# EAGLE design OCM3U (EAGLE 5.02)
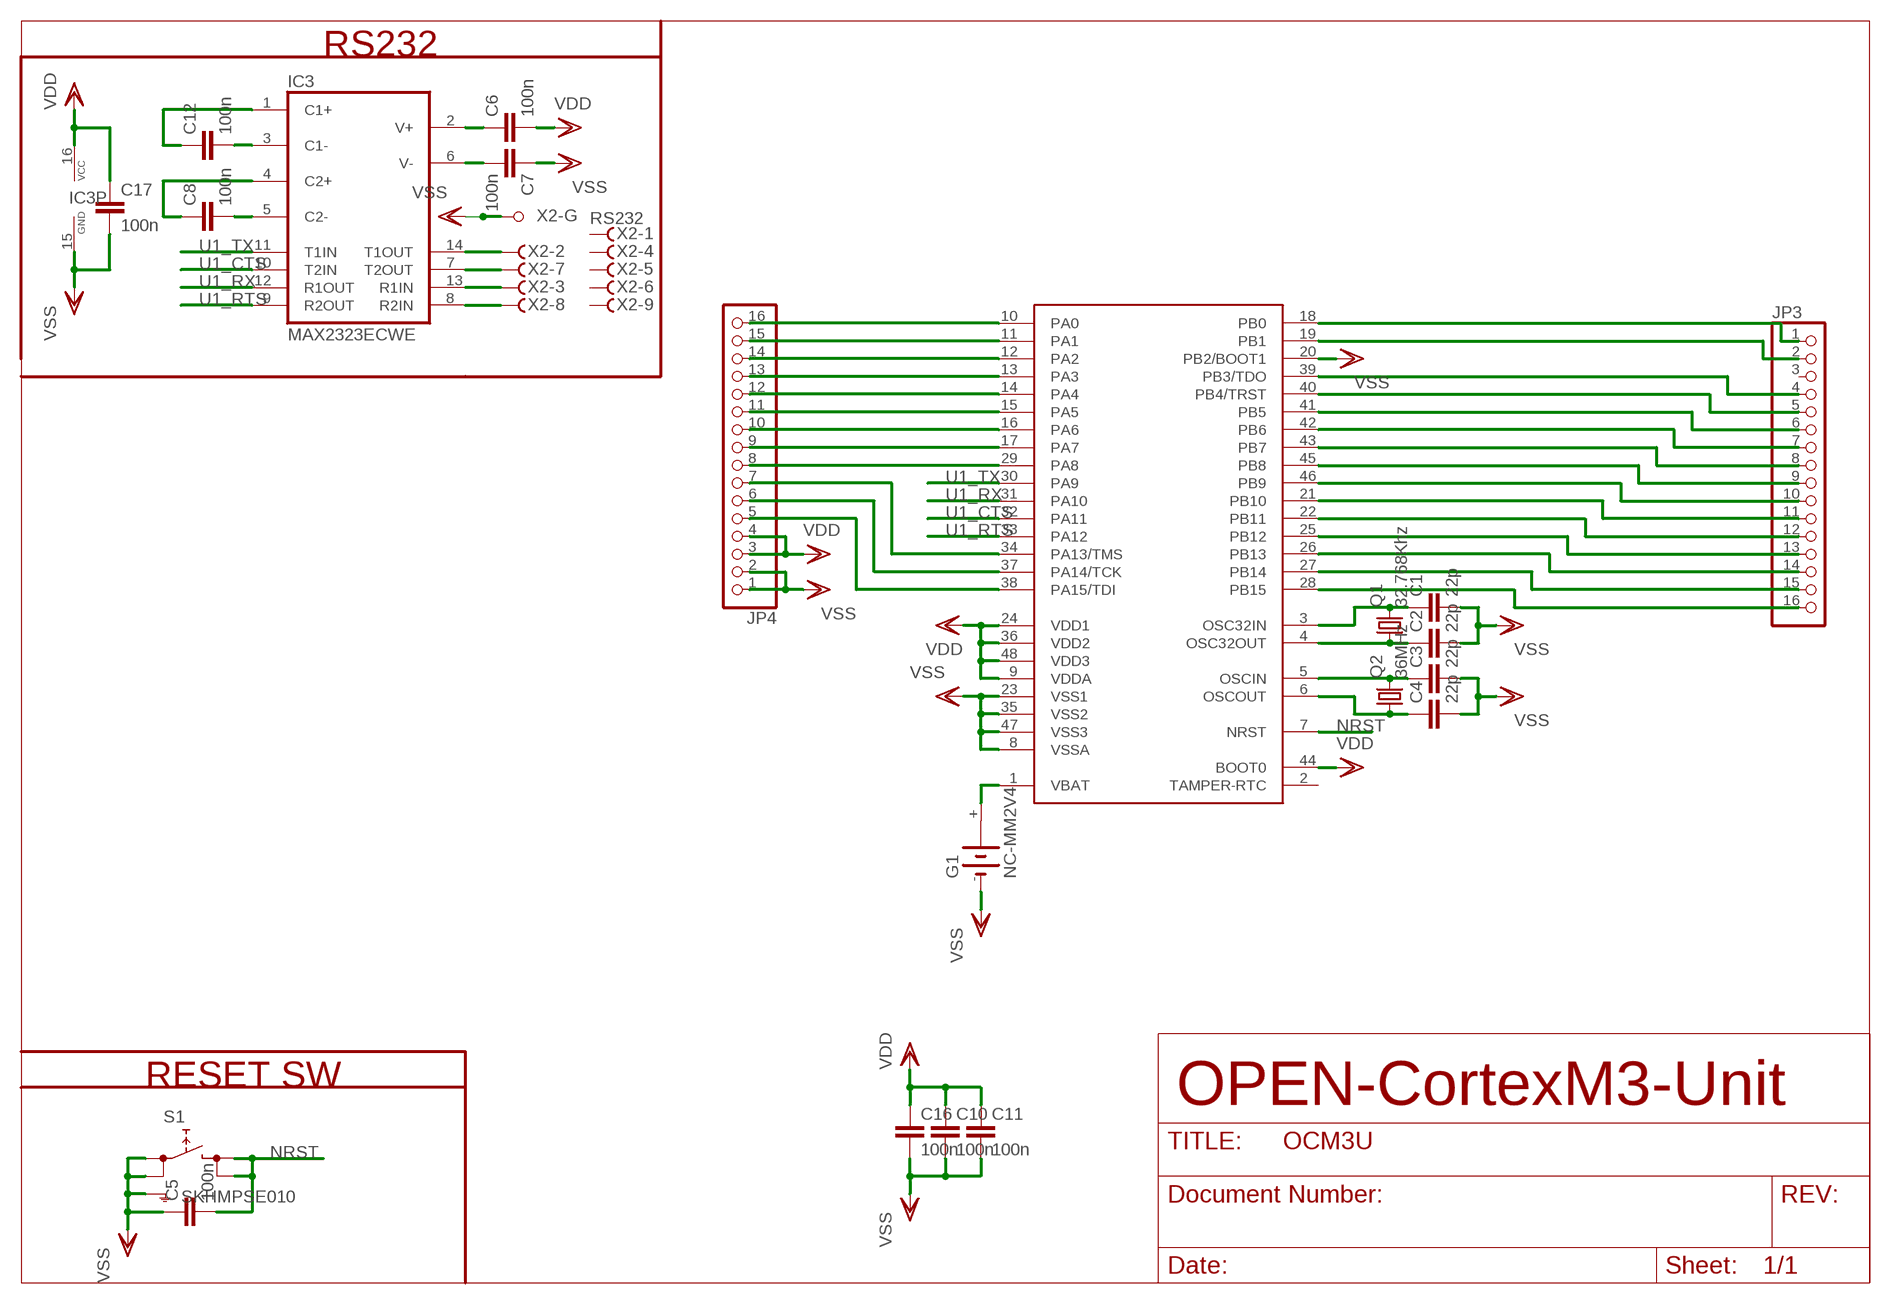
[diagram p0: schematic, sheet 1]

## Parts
C1  22p  C-EUC0805  [C0805]
C2  22p  C-EUC0805  [C0805]
C3  22p  C-EUC0805  [C0805]
C4  22p  C-EUC0805  [C0805]
C5  100n  C-EUC0805  [C0805]
C6  100n  C-EUC0805  [C0805]
C7  100n  C-EUC0805  [C0805]
C8  100n  C-EUC0805  [C0805]
C10  100n  C-EUC0805  [C0805]
C11  100n  C-EUC0805  [C0805]
C12  100n  C-EUC0805  [C0805]
C16  100n  C-EUC0805  [C0805]
C17  100n  C-EUC0805  [C0805]
G1  NC-MM2V4  [NC-MM]
IC3  MAX2323ECWE  MAX232ECWE  [SO16L]
JP3  PINHD-1X16  [1X16]
JP4  PINHD-1X16  [1X16]
Q1  32.768Khz  CRYSTALHC49UP  [HC49UP]
Q2  36MHz  CRYSTALHC49UP  [HC49UP]
S1  SKHMPSE010  [SKHMPXE010]
U$1  STM32F101C8T6  [LQFP48]
X2  RS232  F09HPS  [F09HP]

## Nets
N$1: G1.+ U$1.1(VBAT)
N$4: C1.1 Q1.2 U$1.3(OSC32IN)
N$5: C2.1 Q1.1 U$1.4(OSC32OUT)
N$6: C3.1 Q2.2 U$1.5(OSCIN)
N$7: C4.1 Q2.1 U$1.6(OSCOUT)
N$8: IC3.13(R1IN) X2.3(-3:F)
N$9: IC3.14(T1OUT) X2.2(-2:F)
N$10: IC3.7(T2OUT) X2.7(-7:F)
N$11: IC3.8(R2IN) X2.8(-8:F)
N$12: C6.1 IC3.2(V+)
N$13: C7.2 IC3.6(V-)
N$14: C12.2 IC3.3(C1-)
N$15: C12.1 IC3.1(C1+)
N$16: C8.1 IC3.4(C2+)
N$17: C8.2 IC3.5(C2-)
N$18: JP3.16 U$1.28(PB15)
N$19: JP3.15 U$1.27(PB14)
N$20: JP3.9 U$1.45(PB8)
N$21: JP3.14 U$1.26(PB13)
N$22: JP3.13 U$1.25(PB12)
N$23: JP3.12 U$1.22(PB11)
N$24: JP3.11 U$1.21(PB10)
N$25: JP3.10 U$1.46(PB9)
N$27: JP3.8 U$1.43(PB7)
N$28: JP3.7 U$1.42(PB6)
N$29: JP3.6 U$1.41(PB5)
N$30: JP3.2 U$1.19(PB1)
N$31: JP3.1 U$1.18(PB0)
N$32: JP4.16 U$1.10(PA0)
N$33: JP4.15 U$1.11(PA1)
N$34: JP4.14 U$1.12(PA2)
N$35: JP4.13 U$1.13(PA3)
N$36: JP4.12 U$1.14(PA4)
N$37: JP4.11 U$1.15(PA5)
N$38: JP4.10 U$1.16(PA6)
N$39: JP4.9 U$1.17(PA7)
N$40: JP4.8 U$1.29(PA8)
N$44: JP3.5 U$1.40(PB4/TRST)
N$45: JP3.4 U$1.39(PB3/TDO)
N$46: JP4.7 U$1.34(PA13/TMS)
N$47: JP4.6 U$1.37(PA14/TCK)
N$48: JP4.5 U$1.38(PA15/TDI)
NRST: C5.2 S1.3(2.1) S1.4(2.2) U$1.7(NRST)
U1_CTS: IC3.10(T2IN) U$1.32(PA11)
U1_RTS: IC3.9(R2OUT) U$1.33(PA12)
U1_RX: IC3.12(R1OUT) U$1.31(PA10)
U1_TX: IC3.11(T1IN) U$1.30(PA9)
VDD: C6.2 C10.1 C11.1 C16.1 C17.1 IC3.16(VCC) JP4.3 JP4.4 U$1.9(VDDA) U$1.24(VDD1) U$1.36(VDD2) U$1.44(BOOT0) U$1.48(VDD3)
VSS: C1.2 C2.2 C3.2 C4.2 C5.1 C7.1 C10.2 C11.2 C16.2 C17.2 G1.- IC3.15(GND) JP4.1 JP4.2 S1.1(1.1) S1.2(1.2) S1.5(SH) U$1.8(VSSA) U$1.20(PB2/BOOT1) U$1.23(VSS1) U$1.35(VSS2) U$1.47(VSS3) X2.G1(-G:G1) X2.G2(-G:G2)
Unconnected: G1.+@1(+) JP3.3 U$1.2(TAMPER-RTC) X2.1(-1:F) X2.4(-4:F) X2.5(-5:F) X2.6(-6:F) X2.9(-9:F)

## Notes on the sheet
- RS232
- RESET SW
- OPEN-CortexM3-Unit

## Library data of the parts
C1-C8 C10-C12 C16 C17 = rcl:C-EU: CAPACITOR, European symbol
G1 = battery:NC-MM2V4: NC ACCU Sonnenschein Mini-Memo NC-MM 2.4 to 4.8 R5 Sonnenschein
IC3 = maxim:MAX232ECWE: RS232 TRANSEIVER
JP3 JP4 = pinhead:PINHD-1X16: PIN HEADER
Q1 Q2 = crystal:CRYSTAL: CRYSTAL
S1 = switch:SKHMP*E010: 6.2 X 6.5mm TACT Switch (SMD) Source: http://www3.alps.co.jp/WebObjects/catalog.woa/PDF/E/Switch/Tact/SKHM/SKHM.PDF
U$1 = stm32F101xx:STM32F101C8T6
X2 = con-subd:F09HPS: SUB-D

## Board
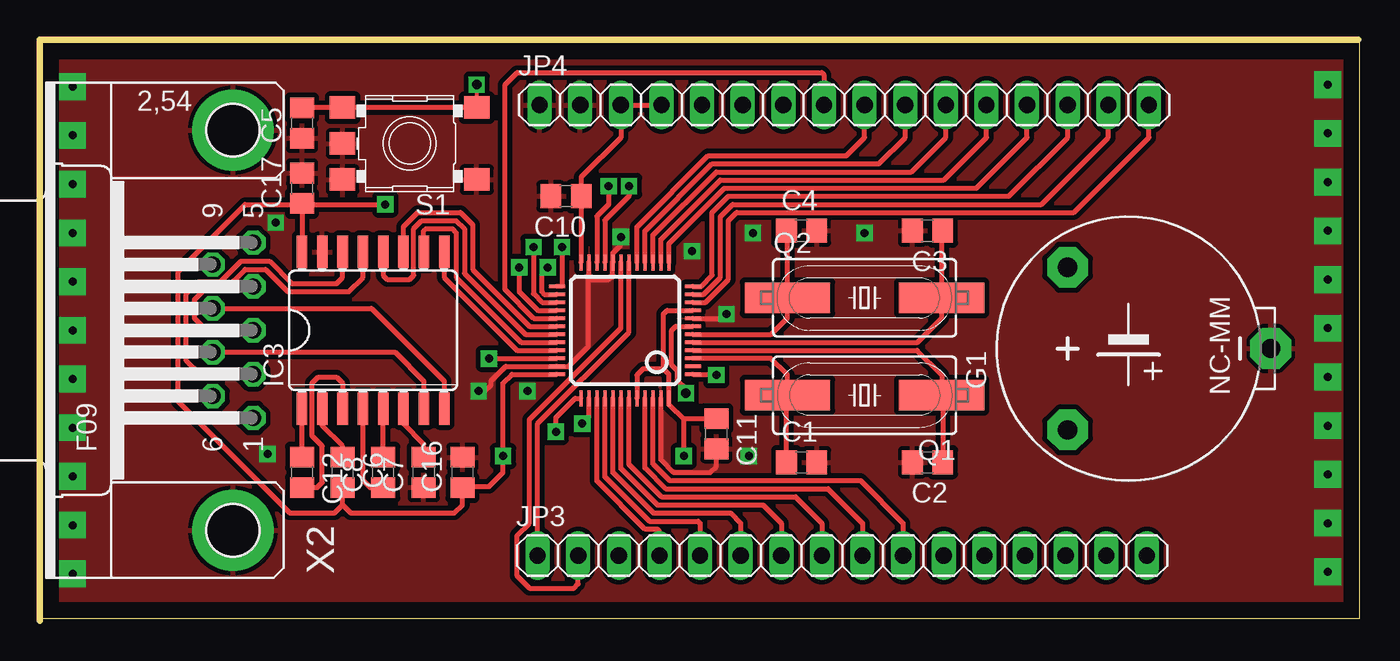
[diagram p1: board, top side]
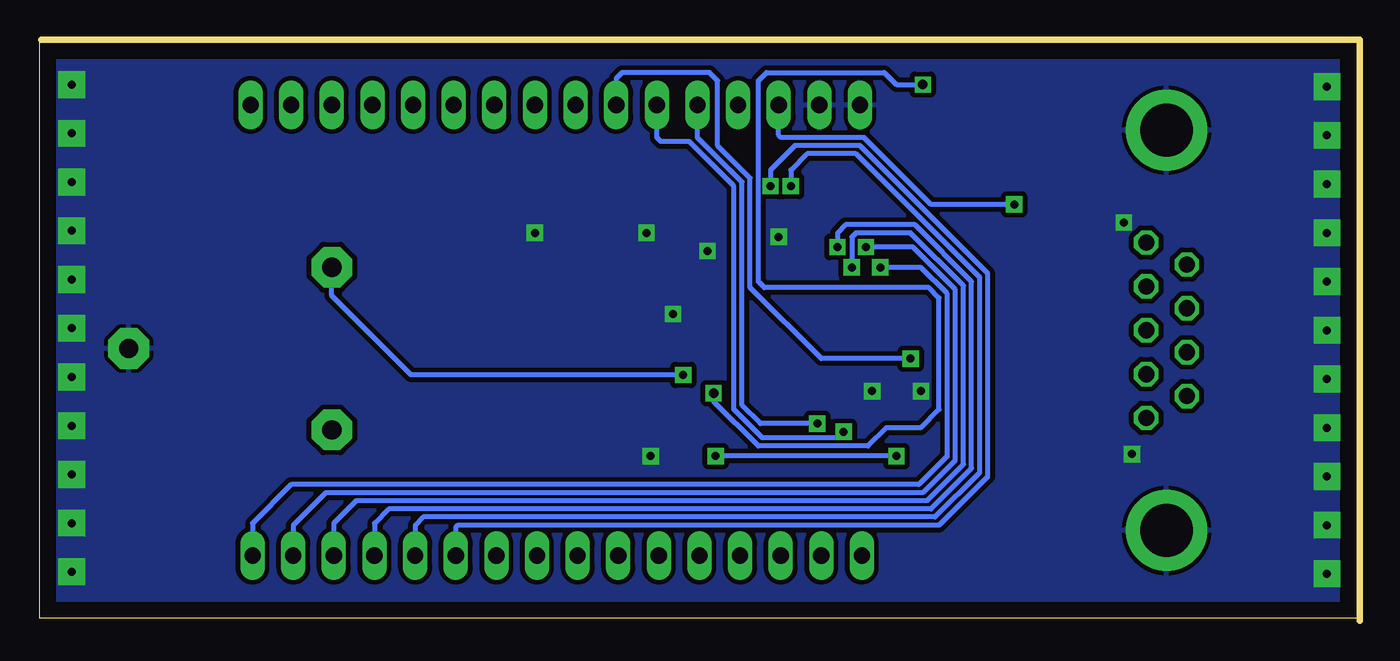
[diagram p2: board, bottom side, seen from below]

Size 82.51 x 36.32 mm. Coordinates in mm from the lower left corner, seen from the top.
Outline: 0,0 0,36.32 82.42,36.32
Outline: 0.04,0.13 82.51,0.13 82.51,36.19 0.04,36.19 0.04,0.13
Copper layers (1*16): Top 0.035mm / dielectric 1.5mm / Bottom 0.035mm
Design rules "default": minimum track width 10mil, minimum drill 24mil, track to track 8mil, track to pad 8mil, pad to pad 8mil, via to via 8mil, smd to smd 8mil, copper to edge 40mil, drill to drill 8mil, minimum pad ring 10mil, minimum via ring 8mil, stop-mask expansion 4mil, vias tented up to drill 0mil, thermal gap 10mil

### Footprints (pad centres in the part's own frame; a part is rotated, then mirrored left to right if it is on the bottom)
C0805 = smd 1.3 x 1.5: 1 -0.95,0; 2 0.95,0
NC-MM = drill 1.194 pad 2.54 octagon: + 5.08,3.81; +@1 -5.08,3.81; - 0,-8.89
SO16L = smd 0.66 x 2.032: 1 -4.445,-4.902; 2 -3.175,-4.902; 3 -1.905,-4.902; 4 -0.635,-4.902; 5 0.635,-4.902; 6 1.905,-4.902; 7 3.175,-4.902; 8 4.445,-4.902; 9 4.445,4.902; 10 3.175,4.902; 11 1.905,4.902; 12 0.635,4.902; 13 -0.635,4.902; 14 -1.905,4.902; 15 -3.175,4.902; 16 -4.445,4.902
1X16 = drill 1.016 long: 1 -19.05,0; 2 -16.51,0; 3 -13.97,0; 4 -11.43,0; 5 -8.89,0; 6 -6.35,0; 7 -3.81,0; 8 -1.27,0; 9 1.27,0; 10 3.81,0; 11 6.35,0; 12 8.89,0; 13 11.43,0; 14 13.97,0; 15 16.51,0; 16 19.05,0
HC49UP = smd 5.334 x 1.93: 1 -4.826,0; 2 4.826,0
SKHMPXE010 = smd 1.6 x 1.4: 1 -4.2,2.25; 2 4.2,2.25; 3 -4.2,-2.25; 4 4.2,-2.25; 5 4.2,0
LQFP48 = smd 0.2 x 1: 1 -2.75,-4.25; 2 -2.25,-4.25; 3 -1.75,-4.25; 4 -1.25,-4.25; 5 -0.75,-4.25; 6 -0.25,-4.25; 7 0.25,-4.25; 8 0.75,-4.25; 9 1.25,-4.25; 10 1.75,-4.25; 11 2.25,-4.25; 12 2.75,-4.25; 25 2.75,4.25; 26 2.25,4.25; 27 1.75,4.25; 28 1.25,4.25; 29 0.75,4.25; 30 0.25,4.25; 31 -0.25,4.25; 32 -0.75,4.25; 33 -1.25,4.25; 34 -1.75,4.25; 35 -2.25,4.25; 36 -2.75,4.25 | smd 1 x 0.2: 13 4.25,-2.75; 14 4.25,-2.25; 15 4.25,-1.75; 16 4.25,-1.25; 17 4.25,-0.75; 18 4.25,-0.25; 19 4.25,0.25; 20 4.25,0.75; 21 4.25,1.25; 22 4.25,1.75; 23 4.25,2.25; 24 4.25,2.75; 37 -4.25,2.75; 38 -4.25,2.25; 39 -4.25,1.75; 40 -4.25,1.25; 41 -4.25,0.75; 42 -4.25,0.25; 43 -4.25,-0.25; 44 -4.25,-0.75; 45 -4.25,-1.25; 46 -4.25,-1.75; 47 -4.25,-2.25; 48 -4.25,-2.75
F09HP = drill 1.016 octagon: 1 -5.486,-1.27; 2 -2.743,-1.27; 3 0,-1.27; 4 2.743,-1.27; 5 5.486,-1.27; 6 -4.115,1.27; 7 -1.372,1.27; 8 1.372,1.27; 9 4.115,1.27 | drill 3.302 pad 5.08 round: G1 -12.522,0; G2 12.522,0

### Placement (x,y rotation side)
C1  47.62,9.91 0 top
C2  55.5,9.91 180 top
C3  55.5,24.38 180 top
C4  47.62,24.38 0 top
C5  16.38,31.11 90 top
C6  18.92,9.27 270 top
C7  24,9.27 90 top
C8  21.46,9.27 90 top
C10  32.89,26.54 180 top
C11  42.29,11.68 270 top
C12  16.38,9.27 270 top
C16  26.42,9.27 90 top
C17  16.38,27.05 90 top
G1  68.07,17.02 90 top
IC3  20.83,18.16 0 top
JP3  50.16,4.06 0 top
JP4  50.29,32.26 0 top
Q1  51.56,14.1 180 top
Q2  51.56,20.19 0 top
S1  23.11,29.84 180 top
U$1  36.58,18.16 90 top
X2  12.06,18.16 90 top

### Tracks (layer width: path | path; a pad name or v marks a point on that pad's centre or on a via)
N$1  (via drill 0.5 pad 1.02)
  Top 0.305: U$1.1 42.25,15.41 v42.29,15.37
  Bottom 0.305: v42.29,15.37 59.31,15.37 64.26,20.32 G1.+
N$4
  Top 0.305: U$1.3 45.69,16.41 46.74,15.37 46.74,14.22 46.86,14.1 Q1.2 46.61,14.1 46.67,14.03 C1.1
N$5
  Top 0.305: U$1.4 54.84,16.91 56.39,15.37 56.39,14.22 | 56.39,13.84 Q1.1 56.39,14.22 | C2.1 56.45,14.16 56.39,14.22
N$6
  Top 0.305: U$1.5 54.88,17.41 56.39,18.92 Q2.2 | Q2.2 56.26,20.32 | C3.1 56.13,24.38 56.39,24.13 Q2.2
N$7
  Top 0.305: U$1.6 45.72,17.91 46.74,18.92 Q2.1 | Q2.1 46.74,20.32 | C4.1 46.74,24.38 Q2.1
N$8
  Top 0.254: IC3.13 20.19,23.24
  Top 0.305: X2.3 10.41,18.16 9.65,18.92 9.65,20.07 10.29,20.7 11.56,20.7 12.83,21.97 14.1,21.97 15.49,20.57 19.3,20.57 20.19,21.46 IC3.13
N$9
  Top 0.305: X2.2 9.98,15.42 9.14,16.26 9.14,20.45 9.91,21.21 11.3,21.21 12.57,22.48 14.35,22.48 15.75,21.08 18.54,21.08 18.92,21.46 IC3.14
N$10
  Top 0.254: IC3.7 24,13.08
  Top 0.305: X2.7 22.2,16.79 24,14.99 IC3.7
N$11
  Top 0.254: IC3.8 25.27,13.08
  Top 0.305: X2.8 20.73,19.53 25.27,14.99 25.27,13.46 25.4,13.33 IC3.8
N$12
  Top 0.305: IC3.2 17.65,12.19 18.92,10.92 C6.1
N$13
  Top 0.305: IC3.6 22.73,12.32 24,11.05 24,10.41 23.88,10.29 C7.2
N$14
  Top 0.305: C12.2 17.34,8.32 17.65,8.64 17.65,10.92 17.02,11.56 17.02,14.86 17.4,15.24 18.54,15.24 18.92,14.86 18.92,13.46 19.05,13.33 IC3.3
N$15
  Top 0.305: C12.1 IC3.1
N$16
  Top 0.305: C8.1 20.64,8.32 20.19,8.76 20.19,12.95 20.07,13.08 20.19,13.21 IC3.4
N$17
  Top 0.305: C8.2 IC3.5
N$18  (via drill 0.5 pad 1.02)
  Top 0.305: U$1.28 31.14,19.41 29.97,20.57 v29.97,22.1
  Bottom 0.305: v29.97,22.1 27.43,22.1 25.78,20.45 25.78,10.29 27.56,8.51 66.8,8.51 69.22,6.1 JP3.16
N$19  (via drill 0.5 pad 1.02)
  Top 0.305: U$1.27 31.4,19.91 30.86,20.45 v30.86,23.37
  Bottom 0.305: v30.86,23.37 27.94,23.37 25.27,20.7 25.27,10.03 27.31,8 64.64,8 66.68,5.97 JP3.15
N$20
  Top 0.305: U$1.45 37.83,9.54 39.12,8.25 49.28,8.25 51.43,6.1 JP3.9 51.43,3.94
N$21  (via drill 0.5 pad 1.02)
  Top 0.305: U$1.26 31.53,20.41 31.37,20.57 31.37,22.1 v31.75,22.1
  Bottom 0.305: v31.75,22.1 31.75,24 31.5,24.26 28.07,24.26 24.77,20.95 24.77,9.78 27.05,7.49 62.74,7.49 64.14,6.1 JP3.14
N$22  (via drill 0.5 pad 1.02)
  Top 0.305: U$1.25 32.64,20.91 v32.64,23.37
  Bottom 0.305: v32.64,23.37 32.64,24.26 32.13,24.77 27.81,24.77 24.26,21.21 24.26,9.53 26.8,6.98 60.71,6.98 61.59,6.1 61.59,4.32 61.72,4.19 JP3.13
N$23  (via drill 0.5 pad 1.02)
  Top 0.305: U$1.22 34.83,25.3 35.56,26.04 v35.56,27.18
  Bottom 0.305: v35.56,27.18 35.56,28.19 34.54,29.21 31.5,29.21 23.75,21.46 23.75,9.27 26.54,6.48 58.55,6.48 59.05,5.97 JP3.12
N$24  (via drill 0.5 pad 1.02)
  Top 0.305: U$1.21 35.33,25.04 36.83,26.54 v36.83,27.18
  Bottom 0.305: v36.83,27.18 36.83,28.19 35.31,29.72 31.24,29.72 23.24,21.72 23.24,9.02 26.29,5.97 56.39,5.97 56.52,5.84 JP3.11
N$25
  Top 0.305: U$1.46 38.33,9.81 39.37,8.76 51.31,8.76 53.98,6.1 JP3.10 53.98,3.94
N$27
  Top 0.305: U$1.43 36.83,9.78 38.86,7.75 47.24,7.75 48.89,6.1 JP3.8
N$28
  Top 0.305: U$1.42 36.33,9.52 38.61,7.24 45.21,7.24 46.35,6.1 JP3.7
N$29
  Top 0.305: U$1.41 35.83,9.26 38.35,6.73 43.18,6.73 43.81,6.1 JP3.6
N$30
  Top 0.305: U$1.19 36.33,18.29 30.61,12.57 30.61,6.1 29.85,5.33 29.85,2.79 30.61,2.03 33.4,2.03 33.66,2.29 JP3.2
N$31
  Top 0.305: U$1.18 36.83,18.03 31.12,12.32 JP3.1
N$32
  Top 0.305: U$1.10 41.63,19.91 43.05,21.34 43.05,25.02 43.56,25.53 64.64,25.53 69.34,30.23 JP4.16
N$33
  Top 0.305: U$1.11 41.49,20.41 42.54,21.46 42.54,25.27 43.31,26.04 62.61,26.04 66.8,30.23 JP4.15
N$34
  Top 0.305: U$1.12 41.36,20.91 42.04,21.59 42.04,25.53 43.05,26.54 60.58,26.54 64.26,30.23 JP4.14
N$35
  Top 0.305: U$1.13 39.33,23.58 42.8,27.05 58.55,27.05 61.72,30.23 JP4.13 61.72,32.38
N$36
  Top 0.305: U$1.14 38.83,23.84 42.54,27.56 56.52,27.56 59.18,30.23 JP4.12
N$37
  Top 0.305: U$1.15 38.33,24.1 42.29,28.07 54.48,28.07 56.64,30.23 JP4.11
N$38
  Top 0.305: U$1.16 37.83,24.36 42.04,28.57 52.45,28.57 54.1,30.23 JP4.10
N$39
  Top 0.305: U$1.17 37.33,24.63 41.78,29.08 50.42,29.08 51.56,30.23 JP4.9
N$40
  Top 0.305: U$1.29 30.87,18.91 29.08,20.7 29.08,33.53 29.85,34.29 48.89,34.29 49.02,34.16 JP4.8 49.02,32.13
N$44
  Top 0.305: U$1.40 35.33,9 38.1,6.22 41.15,6.22 41.27,6.1 JP3.5
N$45
  Top 0.305: U$1.39 34.83,8.73 37.85,5.71 38.61,5.71 38.73,5.59 JP3.4
N$46  (via drill 0.5 pad 1.02)
  Top 0.305: U$1.34 27.91,16.41 v28.07,16.38
  Bottom 0.305: JP4.7 46.48,33.91 46.1,34.29 40.64,34.29 40.13,33.78 40.13,29.72 38.1,27.69 38.1,20.83 33.66,16.38 v28.07,16.38
N$47  (via drill 0.5 pad 1.02)
  Top 0.305: U$1.37 33.47,13.91 32.26,12.7 v32.26,11.81
  Bottom 0.305: JP4.6 43.94,30.23 43.69,29.97 41.91,29.97 39.12,27.18 39.12,13.21 37.34,11.43 32.64,11.43 v32.26,11.81
N$48  (via drill 0.5 pad 1.02)
  Top 0.305: U$1.38 34.33,12.74 v33.91,12.32
  Bottom 0.305: JP4.5 41.4,30.23 38.61,27.43 38.61,13.46 37.46,12.32 v33.91,12.32
NRST  (via drill 0.6)
  Top 0.254: 27.43,32.09 27.43,32.13 27.4,32.09 S1.3 27.31,33.52 v27.31,33.53 | C5.2 16.38,32.13 16.42,32.09
  Top 0.305: U$1.7 39.75,18.41 39.5,18.16 39.5,16 39.88,15.62 39.88,14.99 40.39,14.48 v40.39,14.22 | S1.4 19.05,32.09 19.05,32.13 19.01,32.09 S1.4 | S1.4 16.42,32.09 | S1.3 27.43,32.09 27.56,32 27.47,32.09 S1.4
  Bottom 0.305: v27.31,33.53 28.96,33.53 29.72,34.29 37.08,34.29 37.59,33.78 37.59,21.21 37.21,20.83 26.92,20.83 26.29,20.19 26.29,13.21 27.43,12.06 29.59,12.06 30.73,10.92 37.59,10.92 40.39,13.72 v40.39,14.22
U1_CTS
  Top 0.305: U$1.32 30.09,17.41 26.04,21.46 26.04,24.26 25.78,24.51 24.13,24.51 24,24.38 IC3.10
U1_RTS
  Top 0.254: IC3.9 25.27,23.11
  Top 0.305: U$1.33 29.83,16.91 25.27,21.46 IC3.9
U1_RX
  Top 0.254: 21.46,22.99 IC3.12 21.46,23.11
  Top 0.305: U$1.31 30.35,17.91 26.54,21.72 26.54,24.51 26.04,25.02 23.88,25.02 23.37,24.51 23.37,21.59 23.11,21.34 21.72,21.34 21.46,21.59 21.46,22.86 21.34,22.99 IC3.12
U1_TX
  Top 0.305: U$1.30 30.61,18.41 27.05,21.97 27.05,24.77 26.29,25.53 23.62,25.53 22.73,24.64 IC3.11 22.73,22.99
VDD  (via drill 0.5 pad 1.02)
  Top 0.254: C11.1 42.29,12.57
  Top 0.305: U$1.24 33.83,26.46 33.91,26.54 C10.1 33.84,27.75 36.32,30.23 JP4.3 JP4.4 | U$1.9 39.22,19.41 38.99,19.18 38.99,15.75 | 38.99,15.75 39.33,15.41 U$1.48 39.33,13.51 40.26,12.57 | U$1.44 37.33,15.35 37.72,15.75 38.99,15.75 | v40.26,10.29 40.26,12.57 | C11.1 40.32,12.63 40.26,12.57 | U$1.36 29.51,15.41 28.96,14.86 v28.96,10.29 28.96,9.27 28.07,8.38 26.42,8.38 | 18.92,7.24 C6.2 | 18.92,7.24 19.43,6.73 25.91,6.73 26.42,7.24 26.42,8.38 | 26.42,8.38 C16.1 | 18.92,7.24 18.42,6.73 15.62,6.73 8.64,13.72 8.64,21.84 12.83,26.04 16.38,26.04 | 16.38,26.04 C17.1 16.38,26.16 | 16.38,26.04 v21.59,26.04 | IC3.16 16.38,22.99 | IC3.16 16.38,23.11 | 16.38,26.04 IC3.16
  Bottom 0.305: v28.96,10.29 v40.26,10.29 | v21.59,26.04 26.8,26.04 30.99,30.23 36.2,30.23 36.32,30.35 36.32,32.38 JP4.3
VSS  (via drill 0.5 pad 1.02, 0.5 pad 1.68)
  Top 0.254: v42.93,19.18 42.53,18.91 | C11.2 42.29,10.79 | 35.81,21.46 35.83,21.47
  Top 0.305: 34.33,21.46 34.33,21.37 34.29,21.34 35.56,21.34 35.81,21.59 | 34.33,21.46 U$1.23 | 35.81,21.59 35.81,21.46 | 35.81,21.59 35.81,22.48 35.83,22.48 U$1.20 35.83,23 36.32,23.5 v36.32,24 | U$1.8 42.66,18.91 v42.93,19.18 | 34.33,21.46 34.29,21.46 34.29,17.14 33.06,15.91 U$1.35 29.12,15.91 28.19,14.99 28.19,14.73 27.81,14.35 v27.43,14.35 | U$1.47 38.83,10.07 39.62,9.27 41.91,9.27 42.29,9.65 C11.2
  other vias: 80.52,33.53 80.52,30.48 80.52,27.43 80.52,24.38 80.52,21.34 80.52,18.29 80.52,15.24 80.52,12.19 80.52,3.05 80.52,6.1 80.52,9.14 2.03,33.4 2.03,30.35 2.03,27.3 2.03,24.26 2.03,21.21 2.03,18.16 2.03,15.11 2.03,12.06 2.03,2.92 2.03,5.97 2.03,9.02 40.77,23.11 44.58,24.26 51.56,24.26 30.48,14.35 14.73,24.89 14.22,10.41 44.32,10.29
  pour Top (isolate 0.305): -9.02,38.61 91.06,38.48 91.06,-5.33 -9.02,-5.21
  pour Bottom (isolate 0.305): -9.27,39.75 91.31,40.26 91.31,-4.7 -9.27,-5.21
